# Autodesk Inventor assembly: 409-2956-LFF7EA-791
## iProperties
Created: 2010-09
Part Number: 409-2956-LFF7EA-791
Document SubType Name: Weldment
Designer: S. Boerckel
Weld Material: Welded Aluminum-6061
Mass: 6030.48 g
Surface Area: 2434.61 cm^2
Volume: 768.052 cm^3
Density: 7.85166 g/cm^3
Description: DISCHARGE PIPE STAND
User Status: WELD
Material: WELDMENT
SMR: =<MATERIAL>
Author: S. Boerckel
Revision Number: A
